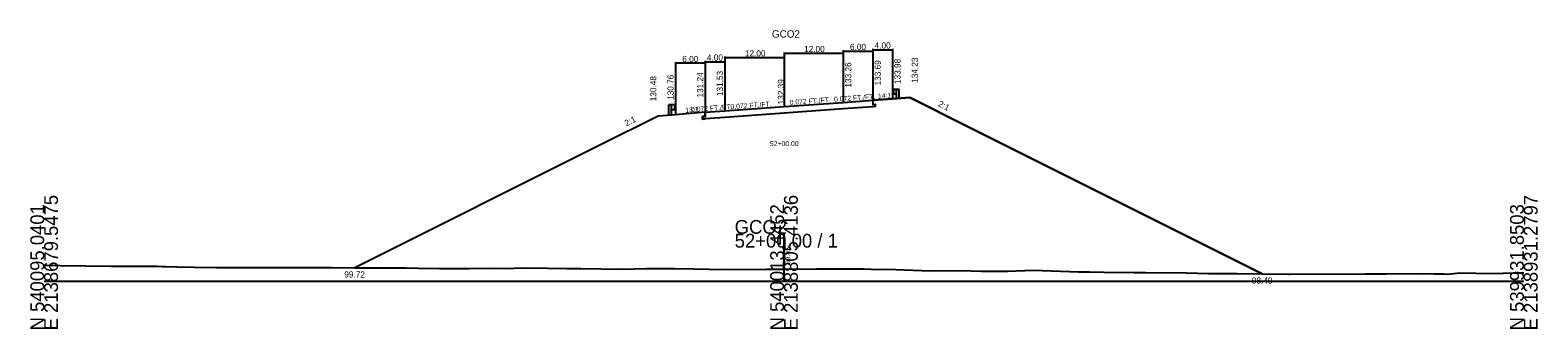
# Model space of a CAD drawing. Extents: x -14327 to 8886, y -10 to 39048.
# Drawn here: x 1997.2 to 2302.8, y 3990.3 to 4050.9 of the extents above; entities that cross this region are included whole.
import ezdxf

# ---------------------------------------------------------------- set-up
doc = ezdxf.new("R2010")
doc.units = 0
for name, color, linetype in [('Level 1', 7, 'Continuous'), ('Level 5', 7, 'Continuous'), ('Level 53', 7, 'Continuous'), ('Level 54', 7, 'Continuous'), ('Level 55', 7, 'Continuous'), ('Level 7', 7, 'Continuous'), ('RD_GPK_XS_Cell', 7, 'Continuous'), ('RD_XS_EwShp', 7, 'Continuous'), ('RD_XS_ExGround', 7, 'Continuous'), ('RD_XS_Pave', 7, 'Continuous'), ('RD_XS_TX_Baseline', 7, 'Continuous'), ('RD_XS_TX_Elev_EX', 7, 'Continuous'), ('RD_XS_TX_Elev_PR', 7, 'Continuous'), ('RD_XS_TX_Station', 7, 'Continuous')]:
    doc.layers.add(name, color=color, linetype=linetype)

msp = doc.modelspace()

# ---------------------------------------------------------------- linework, layer by layer
at = {"layer": 'Level 1'}
for p, q in [((2172.02, 4038.79), (2172.14, 4038.88)), ((2172.02, 4038.69), (2172.14, 4038.6)), ((2172.02, 4038.26), (2172.14, 4038.35)), ((2172.02, 4038.16), (2172.14, 4038.07)), ((2172.15, 4038.89), (2172.23, 4038.9)), ((2172.15, 4038.06), (2172.23, 4038.05)), ((2172.16, 4038.55), (2172.16, 4038.4)), ((2172.23, 4038.96), (2172.23, 4037.99)), ((2172.23, 4038.96), (2172.78, 4038.96)), ((2172.78, 4036.98), (2172.78, 4038.96)), ((2172.78, 4038.96), (2173.34, 4038.96)), ((2173.34, 4036.98), (2173.34, 4038.96)), ((2126.66, 4033.76), (2126.66, 4035.75)), ((2127.22, 4035.75), (2126.66, 4035.75)), ((2127.22, 4033.76), (2127.22, 4035.75)), ((2127.77, 4035.75), (2127.22, 4035.75)), ((2127.77, 4035.75), (2127.77, 4034.77)), ((2127.85, 4035.67), (2127.77, 4035.69)), ((2127.84, 4035.34), (2127.84, 4035.18)), ((2127.98, 4035.58), (2127.86, 4035.67)), ((2127.98, 4035.48), (2127.86, 4035.38)), ((2127.98, 4035.05), (2127.86, 4035.14)), ((2172.23, 4037.99), (2172.78, 4037.99)), ((2127.77, 4034.77), (2127.22, 4034.77)), ((2127.85, 4034.85), (2127.77, 4034.84)), ((2127.98, 4034.95), (2127.86, 4034.85))]:
    msp.add_line(p, q, dxfattribs=at)
for centre, radius, start, end in [((2172.07, 4038.74), 0.0651, 129.0336, 230.9663), ((2172.07, 4038.21), 0.0651, 129.0336, 230.9663), ((2172.09, 4038.4), 0.0651, 302.9895, 0), ((2172.15, 4038.86), 0.026, 90, 129.0505), ((2172.09, 4038.55), 0.0651, 0, 45), ((2172.15, 4038.09), 0.026, 230.9496, 270), ((2127.91, 4035.34), 0.0651, 135, 180), ((2127.91, 4035.18), 0.0651, 180, 237.0105), ((2127.85, 4035.65), 0.026, 50.9495, 90), ((2127.93, 4035.53), 0.0651, 309.0337, 50.9664), ((2127.93, 4035), 0.0651, 309.0337, 50.9664), ((2127.85, 4034.87), 0.026, 270, 309.0504)]:
    msp.add_arc(centre, radius, start, end, dxfattribs=at)
at = {"layer": 'Level 5'}
for p, q in [((2168, 4035.35), (2162, 4034.92)), ((2168, 4036.69), (2168, 4035.85)), ((2168, 4035.85), (2168.5, 4035.89)), ((2168.5, 4035.39), (2168, 4035.35)), ((2168.5, 4035.89), (2168.5, 4035.39)), ((2134, 4033.41), (2133.5, 4033.37)), ((2133.5, 4033.37), (2133.5, 4032.87)), ((2133.5, 4032.87), (2134, 4032.91)), ((2134, 4034.24), (2134, 4033.41)), ((2138, 4033.19), (2134, 4032.91)), ((2150, 4034.06), (2138, 4033.19)), ((2162, 4034.92), (2150, 4034.06))]:
    msp.add_line(p, q, dxfattribs=at)
at = {"layer": 'Level 54'}
for p, q in [((2128, 4044.39), (2128, 4033.96)), ((2134, 4044.19), (2128, 4044.19)), ((2134, 4044.68), (2134, 4034.44)), ((2134, 4044.48), (2138, 4044.48)), ((2134, 4044.39), (2134, 4034.44)), ((2138, 4045.54), (2138, 4034.73)), ((2138, 4045.34), (2150, 4045.34)), ((2138, 4044.68), (2138, 4034.73)), ((2150, 4046.41), (2150, 4035.59)), ((2150, 4046.21), (2162, 4046.21)), ((2150, 4045.54), (2150, 4035.59)), ((2162, 4046.84), (2162, 4036.46)), ((2162, 4046.64), (2168, 4046.64)), ((2162, 4046.41), (2162, 4036.46)), ((2168, 4047.13), (2168, 4036.89)), ((2168, 4046.93), (2172, 4046.93)), ((2168, 4046.84), (2168, 4036.89)), ((2172, 4047.13), (2172, 4037.18))]:
    msp.add_line(p, q, dxfattribs=at)
at = {"layer": 'Level 7'}
for p, q in [((2168, 4036.69), (2172, 4036.98)), ((2172, 4036.98), (2175.5, 4037.23)), ((2175.5, 4037.23), (2187.5, 4031.23)), ((2124.5, 4033.48), (2112.5, 4027.48)), ((2128, 4033.76), (2124.5, 4033.48)), ((2134, 4034.24), (2128, 4033.76)), ((2187.5, 4031.23), (2246.97, 4001.49)), ((2112.5, 4027.48), (2062.98, 4002.72))]:
    msp.add_line(p, q, dxfattribs=at)
at = {"layer": 'RD_GPK_XS_Cell'}
for p, q in [((2150, 4000), (2150, 4009.59)), ((2000, 4000), (2150, 4000)), ((2150, 4000), (2300, 4000))]:
    msp.add_line(p, q, dxfattribs=at)
at = {"layer": 'RD_XS_EwShp'}
msp.add_lwpolyline([(2062.98, 4002.72), (2064.49, 4002.71), (2065.38, 4002.71), (2073.4, 4002.66), (2075.91, 4002.59), (2080.14, 4002.57), (2086.27, 4002.58), (2090.82, 4002.61), (2093.55, 4002.56), (2096.91, 4002.72), (2102.07, 4002.6), (2105.95, 4002.57), (2108.83, 4002.54), (2117.13, 4002.41), (2122.15, 4002.53), (2127.73, 4002.55), (2131.73, 4002.47), (2137.95, 4002.38), (2146.48, 4002.42), (2148.43, 4002.44), (2150, 4002.45), (2156.67, 4002.49), (2158.93, 4002.48), (2166.17, 4002.46), (2169.17, 4002.38), (2170.91, 4002.4), (2179.68, 4002.1), (2185.82, 4002.15), (2189.99, 4002.04), (2195.37, 4002), (2200.52, 4002.23), (2209.72, 4001.86), (2211.93, 4001.86), (2214.84, 4001.82), (2220.91, 4001.73), (2223.38, 4001.71), (2231.61, 4001.66), (2236.09, 4001.57), (2241.81, 4001.57), (2246.97, 4001.49), (2187.5, 4031.23), (2175.5, 4037.23), (2172, 4036.98), (2168, 4036.69), (2168, 4035.85), (2168.5, 4035.89), (2168.5, 4035.39), (2168, 4035.35), (2162, 4034.92), (2150, 4034.06), (2138, 4033.19), (2134, 4032.91), (2133.5, 4032.87), (2133.5, 4033.37), (2134, 4033.41), (2134, 4034.24), (2128, 4033.76), (2124.5, 4033.48), (2112.5, 4027.48)], close=True, dxfattribs=at)
at = {"layer": 'RD_XS_ExGround'}
for p, q in [((2000, 4003.2), (2003.26, 4003.17)), ((2003.26, 4003.17), (2008.41, 4003.12)), ((2008.41, 4003.12), (2013.59, 4003.06)), ((2013.59, 4003.06), (2022.92, 4003)), ((2022.92, 4003), (2024.02, 4002.99)), ((2024.02, 4002.99), (2024.65, 4002.98)), ((2024.65, 4002.98), (2026.9, 4002.92)), ((2026.9, 4002.92), (2030.38, 4002.83)), ((2030.38, 4002.83), (2034.96, 4002.79)), ((2034.96, 4002.79), (2043.42, 4002.76)), ((2043.42, 4002.76), (2046.42, 4002.77)), ((2046.42, 4002.77), (2052.13, 4002.76)), ((2052.13, 4002.76), (2058.26, 4002.73)), ((2058.26, 4002.73), (2064.49, 4002.71)), ((2064.49, 4002.71), (2065.38, 4002.71)), ((2065.38, 4002.71), (2073.4, 4002.66)), ((2073.4, 4002.66), (2075.91, 4002.59)), ((2075.91, 4002.59), (2080.14, 4002.57)), ((2080.14, 4002.57), (2086.27, 4002.58)), ((2086.27, 4002.58), (2090.82, 4002.61)), ((2090.82, 4002.61), (2093.55, 4002.56)), ((2093.55, 4002.56), (2096.91, 4002.72)), ((2096.91, 4002.72), (2102.07, 4002.6)), ((2102.07, 4002.6), (2105.95, 4002.57)), ((2105.95, 4002.57), (2108.83, 4002.54)), ((2108.83, 4002.54), (2117.13, 4002.41)), ((2117.13, 4002.41), (2122.15, 4002.53)), ((2122.15, 4002.53), (2127.73, 4002.55)), ((2127.73, 4002.55), (2131.73, 4002.47)), ((2131.73, 4002.47), (2137.95, 4002.38)), ((2137.95, 4002.38), (2146.48, 4002.42)), ((2146.48, 4002.42), (2148.43, 4002.44)), ((2148.43, 4002.44), (2150, 4002.45)), ((2150, 4002.45), (2156.67, 4002.49)), ((2156.67, 4002.49), (2158.93, 4002.48)), ((2158.93, 4002.48), (2166.17, 4002.46)), ((2166.17, 4002.46), (2169.17, 4002.38)), ((2169.17, 4002.38), (2170.91, 4002.4)), ((2170.91, 4002.4), (2179.68, 4002.1)), ((2179.68, 4002.1), (2185.82, 4002.15)), ((2185.82, 4002.15), (2189.99, 4002.04)), ((2189.99, 4002.04), (2195.37, 4002)), ((2195.37, 4002), (2200.52, 4002.23)), ((2200.52, 4002.23), (2209.72, 4001.86)), ((2209.72, 4001.86), (2211.93, 4001.86)), ((2211.93, 4001.86), (2214.84, 4001.82)), ((2214.84, 4001.82), (2220.91, 4001.73)), ((2220.91, 4001.73), (2223.38, 4001.71)), ((2223.38, 4001.71), (2231.61, 4001.66)), ((2231.61, 4001.66), (2236.09, 4001.57)), ((2236.09, 4001.57), (2241.81, 4001.57)), ((2241.81, 4001.57), (2252.12, 4001.41)), ((2252.12, 4001.41), (2252.46, 4001.41)), ((2252.46, 4001.41), (2267.9, 4001.49)), ((2267.9, 4001.49), (2272.1, 4001.45)), ((2272.1, 4001.45), (2279.75, 4001.57)), ((2279.75, 4001.57), (2281.92, 4001.44)), ((2281.92, 4001.44), (2282.36, 4001.46)), ((2282.36, 4001.46), (2283.85, 4001.44)), ((2283.85, 4001.44), (2284.61, 4001.42)), ((2284.61, 4001.42), (2287.03, 4001.68)), ((2287.03, 4001.68), (2293.59, 4001.57)), ((2293.59, 4001.57), (2298.04, 4001.67)), ((2298.04, 4001.67), (2300, 4001.67))]:
    msp.add_line(p, q, dxfattribs=at)
at = {"layer": 'RD_XS_Pave'}
for p, q in [((2138, 4034.53), (2150, 4035.39)), ((2150, 4035.39), (2162, 4036.26)), ((2162, 4036.26), (2168, 4036.69)), ((2134, 4034.24), (2138, 4034.53))]:
    msp.add_line(p, q, dxfattribs=at)

# ---------------------------------------------------------------- texts
at = {"layer": 'Level 53'}
for s, rotation, p in [('133.26', 90, (2163.63, 4039.26)), ('133.69', 90, (2169.63, 4039.69)), ('133.98', 90, (2173.63, 4039.98)), ('134.23', 90, (2177.13, 4040.23)), ('130.48', 90, (2124.12, 4036.48)), ('130.76', 90, (2127.62, 4036.76)), ('131.24', 90, (2133.62, 4037.24)), ('131.53', 90, (2137.62, 4037.53)), ('2:1', 333.4349, (2181.11, 4035.54)), ('2:1', 26.5651, (2118.05, 4031.37))]:
    msp.add_text(s, height=1.25, rotation=rotation, dxfattribs=at).set_placement(p)
for s, p in [('99.72', (2060.85, 4000.72)), ('98.49', (2244.86, 3999.49))]:
    msp.add_text(s, height=1.25, dxfattribs=at).set_placement(p)
at = {"layer": 'Level 54'}
for s, p in [('12.00', (2154.07, 4046.46)), ('6.00', (2163.37, 4046.89)), ('4.00', (2168.37, 4047.18)), ('6.00', (2129.37, 4044.44)), ('4.00', (2134.37, 4044.73)), ('12.00', (2142.07, 4045.59))]:
    msp.add_text(s, height=1.25, dxfattribs=at).set_placement(p)
at = {"layer": 'Level 55'}
for s, rotation, p in [('14:1', 4.1182, (2169.08, 4037.02)), ('13:1', 4.5739, (2130.03, 4034.17)), ('0.072 FT./FT.', 4.1182, (2131.18, 4034.29)), ('0.072 FT./FT.', 4.1182, (2139.18, 4034.86)), ('0.072 FT./FT.', 4.1182, (2151.18, 4035.73)), ('0.072 FT./FT.', 4.1182, (2160.18, 4036.38))]:
    msp.add_text(s, height=1, rotation=rotation, dxfattribs=at).set_placement(p)
at = {"layer": 'RD_GPK_XS_Cell'}
for s, p in [('E 2138679.5475', (2002.8, 3990)), ('E 2138805.4136', (2152.8, 3990)), ('E 2138931.2797', (2302.8, 3990)), ('N 540095.0401', (2000, 3990)), ('N 540013.4452', (2150, 3990)), ('N 539931.8503', (2300, 3990))]:
    msp.add_text(s, height=2.8, rotation=90, dxfattribs=at).set_placement(p)
for s, p in [('GCO2', (2140, 4009.59)), ('52+00.00 / 1', (2140, 4006.79))]:
    msp.add_text(s, height=2.8, dxfattribs=at).set_placement(p)
at = {"layer": 'RD_XS_TX_Baseline'}
msp.add_text('GCO2', height=1.5, dxfattribs=at).set_placement((2147.55, 4049.39))
at = {"layer": 'RD_XS_TX_Elev_EX'}
msp.add_text('99.45', height=1, rotation=90, dxfattribs=at).set_placement((2151.25, 4003.45))
at = {"layer": 'RD_XS_TX_Elev_PR'}
msp.add_text(' 132.39', height=1.25, rotation=90, dxfattribs=at).set_placement((2150, 4035.39))
at = {"layer": 'RD_XS_TX_Station'}
msp.add_text('52+00.00', height=1, dxfattribs=at).set_placement((2147.15, 4027.39))

doc.saveas('drawing.dxf')
